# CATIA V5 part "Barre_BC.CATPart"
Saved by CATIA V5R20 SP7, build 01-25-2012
Part number: Barre_BC
Bounding box of the stored display mesh (mm): x -47.5 to 79.99, y 100 to 190, z -49 to -44
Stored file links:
  D:\IFMA\COURS\2A\projet balance IAO\catia\Barre_BC.CATPart
  D:\IFMA\COURS\2A\projet balance IAO\catia\Ass_projet_balance.CATProduct
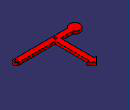
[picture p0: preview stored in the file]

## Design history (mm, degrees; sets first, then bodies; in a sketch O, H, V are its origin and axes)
Set1
  Plane1 "Plan_BC": linked copy from another document
  Point1 "Point.I": linked copy from another document
  Point2 "Point.B": linked copy from another document
  Point3 "Point.C": linked copy from another document
  Point4 "Point.J": linked copy from another document
  Point5 "Point.D": linked copy from another document
Body1 (main body)
  Sketch1 on Plane1, origin (0, 0, -49), H (1, 0, 0), V (0, 1, 0)
    arc A1 centre (75, 110) radius 5 from (75, 105) to (75, 115) ccw
    point P1 (75, 110)
    arc A2 centre (-37.5, 110) radius 5 from (-37.5, 115) to (-37.5, 105) ccw
    point P4 (-37.5, 110)
    line L1 (75, 115) -> (5, 115)
    line L2 (75, 105) -> (-37.5, 105)
    line L3 (-37.5, 115) -> (-5, 115)
    line L4 (-5, 115) -> (-5, 180)
    line L5 (5, 115) -> (5, 180)
    line L6 (5, 180) -> (10, 180)
    point P11 (10, 180)
    line L7 (-5, 180) -> (-10, 180)
    point P12 (-10, 180)
    line L8 (0, 190) -> (-10, 180)
    point P13 (0, 190)
    line L9 (0, 190) -> (10, 180)
    reference projected point E1 (75, 110) from Point2
    reference projected point E2 (75, 110) from Point2
    reference projected point E3 (-37.5, 110) from Point1
    reference projected point E4 (-37.5, 110) from Point1
    reference projected point E5 (0, 110) from Point3
    reference projected point E6 (0, 190) from Point4
    reference projected point E7 (0, 190) from Point4
    reference projected point E8 (0, 190) from Point4
    reference projected point E9 (0, 190) from Point4
    reference projected point E10 (0, 190) from Point4
    reference projected point E11 (0, 190) from Point4
    distance L1 L2 = 10
    distance P1 E1 H = 0
    distance P1 E2 V = 0
    distance P4 E3 V = 0
    distance P4 E4 H = 0
    distance L4 L5 = 10
    distance L5 E5 = 5
    distance P13 E6 V = 0
    distance P13 E7 H = 0
    distance L6 E8 = 10
    distance L7 E9 = 10
    distance P12 E10 H = 10
    distance P11 E11 H = 10
    tangency: L1 A2, L2 A1, L3 A2, L2 A2, A1 L1
    vertical: L4 V, L5 V
    horizontal: L6 H, L7 H
  Pad1: profile Sketch1, direction (0, 0, 1), length 5
  Sketch2 on end face of Pad1, origin (0, 0, -44), H (1, 0, 0), V (0, 1, 0)
    circle A1 centre (0, 110) radius 2.5
    point P1 (0, 110)
    circle A2 centre (75, 110) radius 2.5
    point P2 (75, 110)
    reference projected point E1 (75, 110) from Point2
    reference projected point E2 (0, 110) from Point3
    radius A2 = 2.5
    radius A1 = 2.5
    coincidence: P2 E1, P1 E2
  Pocket1: profile Sketch2, direction (0, 0, 1), through (limit type 6)
  Sketch3 on end face of Pad1, origin (0, 0, -44), H (1, 0, 0), V (0, 1, 0)
    circle A1 centre (-37.5, 110) radius 10
    point P1 (-37.5, 110)
    reference projected point E1 (-37.5, 110) from Point1
    radius A1 = 10
    coincidence: P1 E1
  Pad2: profile Sketch3, direction (0, 0, -1), length 5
